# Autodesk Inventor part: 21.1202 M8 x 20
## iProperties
Created: 2006-02
Part Number: 21.1202 M8 x 20
Material: Steel, Mild
Description: Cylinder Head Cap Screw
Document SubType Name: Modeling
Standard: DIN 7984
Designer: Andy Moles
Standards Organization: DIN
Language: en-US
Size Designation: M8 x 20
Categories: <MemberInstance><Categories><Category DisplayName="Fasteners" InternalName="e4da775c-781d-43d5-af7c-5136215cf5a6" Mnemonic="FSTN"><Category DisplayName="Bolts"
Mass: 12.263 g
Surface Area: 10.1767 cm^2
Volume: 1.56018 cm^3
Density: 7.86 g/cm^3
Author: Andy Moles
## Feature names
1. Body [Revolution]
2. Slot [Extrusion]
3. Fillet1
4. Chamfer1
